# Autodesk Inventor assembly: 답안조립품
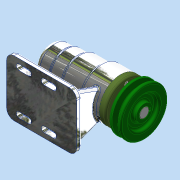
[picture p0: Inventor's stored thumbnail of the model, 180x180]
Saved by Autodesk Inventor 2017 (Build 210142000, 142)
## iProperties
Part Number: 답안조립품
Material: 일반
Document SubType Name: Assembly
Designer: MRC
Author: MRC
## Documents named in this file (12)
- C:\Users\MRC\Desktop\711009V1008\답안조립품.iam
- C:\Users\MRC\Desktop\711009V1008\본체.ipt
- C:\Users\MRC\Desktop\711009V1008\V벨트풀리.ipt
- C:\Users\MRC\Desktop\711009V1008\멈춤나사 M3.ipt
- C:\Users\MRC\Desktop\711009V1008\베어링 6004.ipt
- C:\Users\MRC\Desktop\711009V1008\베어링 51202.ipt
- C:\Users\MRC\Desktop\711009V1008\볼트 M4.ipt
- C:\Users\MRC\Desktop\711009V1008\어댑터슬리브.ipt
- C:\Users\MRC\Desktop\711009V1008\오일 실 20x35x7.ipt
- C:\Users\MRC\Desktop\711009V1008\축.ipt
- C:\Users\MRC\Desktop\711009V1008\커버.ipt
- C:\Users\MRC\Desktop\711009V1008\키 5x5.ipt
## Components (1 placed, 1 different names)
1. V벨트풀리:1
